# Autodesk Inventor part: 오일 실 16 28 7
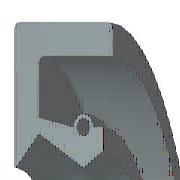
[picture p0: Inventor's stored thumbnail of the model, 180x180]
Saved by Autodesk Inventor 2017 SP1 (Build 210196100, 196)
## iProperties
Created: 2012-02
Part Number: 오일 실 16 28 7
Material: 고무
Description: 오일-실
Document SubType Name: Modeling
Standard: KS B 2804
Designer: mduedu
Standards Organization: KS
Language: ko-KR
Size Designation: D - 16 28 7
Categories: <MemberInstance><Categories><Category DisplayName="샤프트 부품" InternalName="7f7aeb1f-a693-4053-b835-cee3144e0d98" Mnemonic="SHFT"><Category DisplayName="실링" Intern
Density: 0.93 g/cm^3
Appearance: 고무 - 검은색 - 버전 1.1
IsCustomPart: 1
Author: mduedu
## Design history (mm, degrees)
revolve "본체" stored, may be unused: angle "d17" = 90 deg
revolve "스프링1" stored, may be unused: angle "d18" = 90 deg
fillet "모깎기3" dims "d43" = 0.5
body "Solid1"
sketch "스케치1"
  geometry: L1 (0, 14)-(7, 14); L2 (7, 12.25)-(1.75, 12.25); L3 (1.75, 9.75)-(4.9, 8); L4 (4.9, 8)-(0, 8); L5 (0, 0)-(9.586, 0) reference; L6 (4.9, 8)-(6.3, 8.875); L7 (0, 18)-(0, -3) reference; L8 (-1.941, 0)-(11.507, 0) reference; L9 (4.2, 10.1)-(1.75, 10.59); L10 (1.75, 10.59)-(1.75, 12.25); L11 (0, 14)-(0, 8.088); L12 (4.9, 8)-(0, 8); L13 (1.75, 9.75)-(0.152, 8.028); L14 (7, 14)-(7, 12.25); L15 (5.6, 10.1)-(6.3, 10.1); L16 (6.3, 10.1)-(6.3, 8.875); C1 r 0.455 at (4.9, 10.1); A1 r 0.7 centre (4.9, 10.1) between (5.6, 10.1) and (4.2, 10.1); A2 r 0.088 centre (0.088, 8.088) between (0, 8.088) and (0.152, 8.028); 1 further point
  constraints: 28 end point, 5 horizontal alignment, 5 point on line, 4 point on circle, 4 vertical alignment, 3 centre point, 3 tangent, 2 collinear, 2 horizontal, 2 perpendicular, 1 coincident, 1 parallel
  dimensions: "d0" = 28 diameter of L1 L5 (= SD2); "d1" = 1.75 distance of L1.end L2.start (= SD); "d2" = 0.91 diameter of C1 (= SPDI); "d3" = 1.4 diameter of A1 (= SPDA); "d4" = 16 diameter of L3.end L5 (= NND); "d5" = 19.5 diameter of L3.start L5 (= TKDM); "d7" = 21.18 diameter of L9.end L5 (= TKDM + 0.24 x SWDT); "d8" = 1.75 distance between parallel lines of L11 L10 (= SD); "d9" = 4.9 distance from line of L11 C1.centre (= SPDST); "d10" = 20.2 diameter of C1.centre L5 (= HLDM); "d11" = 0.0875 radius of A2 (= 0.25 x LAB); "d12" = 6.3 distance between parallel lines of L11 L16 (= SDI); "d13" = 17.75 diameter of L6.end L5 (= ABDM); "d14" = 7 distance from line of L11 L1.end (= SWDT)
fillet "모깎기1" dims "d6" = 0.3 (= RR)
other parameters: "SD2" = 28 [user parameter; used in 1 equation term], "SWDT" = 7 [user parameter; used in 2 equation terms], "RR" = 0.3 [user parameter; used in 1 equation term], "SD" = 1.75 [user parameter; used in 2 equation terms], "NND" = 16 [user parameter; used in 1 equation term], "SPDA" = 1.4 [user parameter; used in 1 equation term], "SPDI" = 0.91 [user parameter; used in 1 equation term], "TKDM" = 19.5 [user parameter; used in 2 equation terms], "HLDM" = 20.2 [user parameter; used in 1 equation term], "ABDM" = 17.75 [user parameter; used in 1 equation term], "SDI" = 6.3 [user parameter; used in 1 equation term], "SPDST" = 4.9 [user parameter; used in 1 equation term], "LAB" = 0.35 [user parameter; used in 1 equation term], "d15" = 0, "d16" = 0, "d19" = 0
